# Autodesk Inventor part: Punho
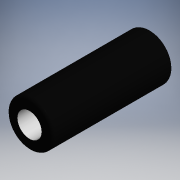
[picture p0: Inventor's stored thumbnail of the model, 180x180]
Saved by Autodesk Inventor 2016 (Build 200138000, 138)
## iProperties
Created: 2016-02
Part Number: Punho
Material: ABS Plastic
Document SubType Name: Modeling
Designer: Vertex
Density: 1.06 g/cm^3
Appearance: Smooth - White
Mass: 42.7251 g
Surface Area: 124.073 cm^2
Volume: 40.3067 cm^3
Author: Vertex
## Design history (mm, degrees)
sketch "Sketch1"
  geometry: C1 r 8 at (0, 0); C2 r 15 at (0, 0); 1 further point
  constraints: 2 centre point, 2 coincident
  dimensions: "d0" = 16 diameter of C1; "d1" = 30 diameter of C2
extrude "Extrusion1" new body sketch "Sketch1" distance "d2" = 80; taper "d3" = 0 deg
fillet "Fillet1" dims "d4" = 2
body "Solid1"
